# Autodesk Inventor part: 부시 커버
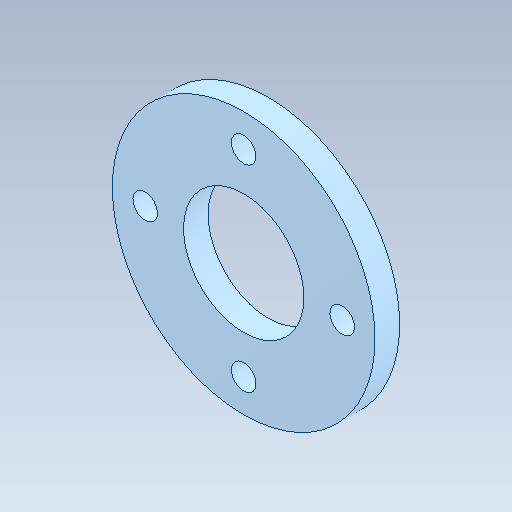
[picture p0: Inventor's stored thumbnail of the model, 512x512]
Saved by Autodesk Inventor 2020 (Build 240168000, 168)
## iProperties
Created: 2024-05
Part Number: 부시 커버
Material: 강철, 연강
Document SubType Name: Modeling
Designer: oem
Density: 7.85 g/cm^3
Appearance: 기본값
Author: jhkim
Sending System: Autodesk Inventor 2025
Preprocessor: ST-DEVELOPER v20
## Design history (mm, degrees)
feature "솔리드1"
node "솔리드2"
